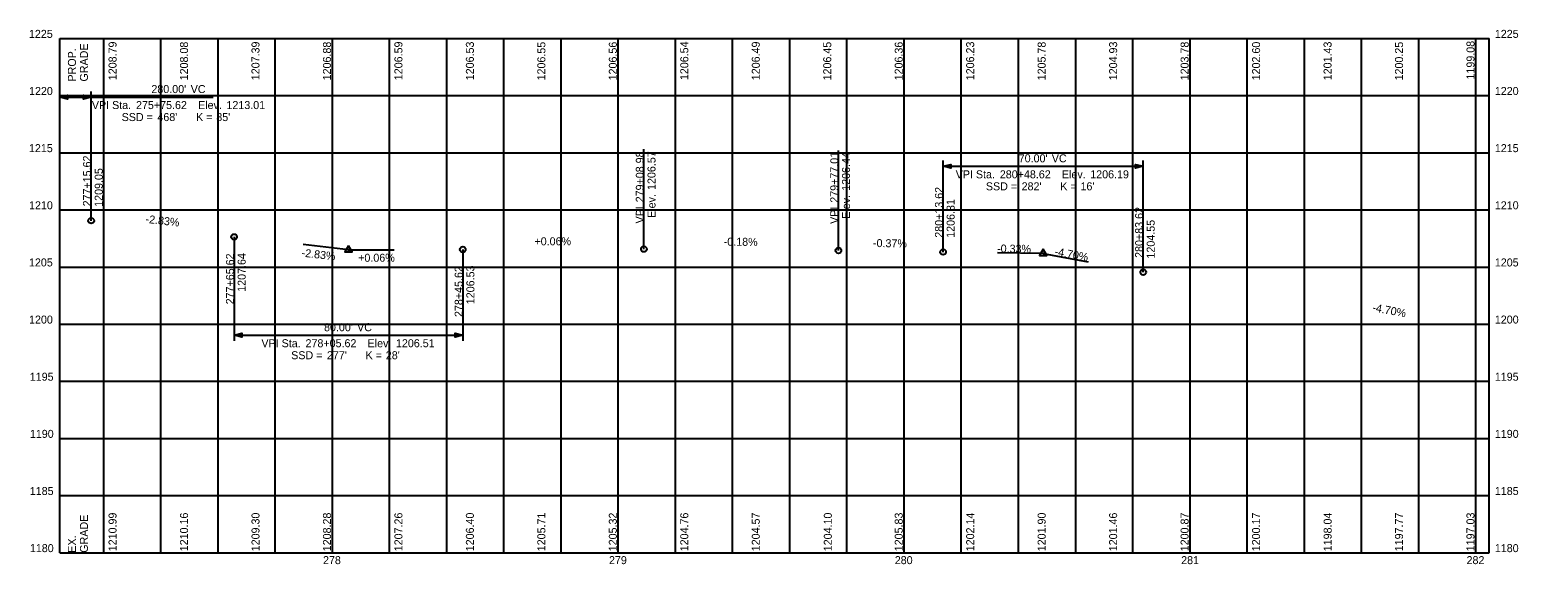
# Model space of a CAD drawing. Extents: x 894 to 1415, y 1176 to 1363.
import ezdxf

# ---------------------------------------------------------------- set-up
doc = ezdxf.new("R2010")
doc.units = 0
for name, color, linetype in [('GE_P_Alignment_100_Bearings', 7, 'Continuous'), ('GE_P_Alignment_100_Cardinal_Points', 7, 'Continuous'), ('GE_P_Alignment_100_Curve_Data', 7, 'Continuous'), ('GE_P_Alignment_100_Stations', 7, 'Continuous'), ('PF_P_Grade_Line', 7, 'Continuous'), ('SC_Scratch1', 7, 'Continuous')]:
    doc.layers.add(name, color=color, linetype=linetype)

msp = doc.modelspace()

# ---------------------------------------------------------------- linework, layer by layer
at = {"layer": 'GE_P_Alignment_100_Bearings'}
for p, q in [((904.62, 1360), (1404.62, 1360)), ((904.62, 1180), (904.62, 1360)), ((920, 1180), (920, 1360)), ((940, 1180), (940, 1360)), ((960, 1180), (960, 1360)), ((980, 1180), (980, 1360)), ((1000, 1180), (1000, 1360)), ((1020, 1180), (1020, 1360)), ((1040, 1180), (1040, 1360)), ((1060, 1180), (1060, 1360)), ((1080, 1180), (1080, 1360)), ((1100, 1180), (1100, 1360)), ((1120, 1180), (1120, 1360)), ((1140, 1180), (1140, 1360)), ((1160, 1180), (1160, 1360)), ((1180, 1180), (1180, 1360)), ((1200, 1180), (1200, 1360)), ((1220, 1180), (1220, 1360)), ((1240, 1180), (1240, 1360)), ((1260, 1180), (1260, 1360)), ((1280, 1180), (1280, 1360)), ((1300, 1180), (1300, 1360)), ((1320, 1180), (1320, 1360)), ((1340, 1180), (1340, 1360)), ((1360, 1180), (1360, 1360)), ((1380, 1180), (1380, 1360)), ((1400, 1180), (1400, 1360)), ((1404.62, 1180), (1404.62, 1360)), ((904.62, 1340), (1404.62, 1340)), ((904.62, 1320), (1404.62, 1320)), ((904.62, 1300), (1404.62, 1300)), ((904.62, 1280), (1404.62, 1280)), ((904.62, 1260), (1404.62, 1260)), ((904.62, 1240), (1404.62, 1240)), ((904.62, 1220), (1404.62, 1220)), ((904.62, 1200), (1404.62, 1200)), ((904.62, 1180), (1404.62, 1180))]:
    msp.add_line(p, q, dxfattribs=at)
at = {"layer": 'GE_P_Alignment_100_Curve_Data'}
for p, q in [((904.62, 1339.58), (904.62, 1339.38)), ((904.62, 1339.48), (915.62, 1339.48)), ((915.62, 1296.21), (915.62, 1341.48)), ((915.62, 1339.38), (915.62, 1339.58)), ((1108.98, 1286.27), (1108.98, 1321.27)), ((1177.01, 1285.78), (1177.01, 1320.78)), ((1213.62, 1285.24), (1213.62, 1317.24)), ((1213.62, 1315.34), (1213.62, 1315.14)), ((1213.62, 1315.24), (1283.62, 1315.24)), ((1283.62, 1278.19), (1283.62, 1317.24)), ((1283.62, 1315.14), (1283.62, 1315.34)), ((965.62, 1290.55), (965.62, 1254.12)), ((1005.62, 1286.02), (989.73, 1287.82)), ((1005.62, 1286.02), (1021.62, 1286.06)), ((1045.62, 1286.12), (1045.62, 1254.12)), ((1005.62, 1286.02), (1005.62, 1286.02)), ((1248.62, 1284.77), (1232.63, 1284.99)), ((1248.62, 1284.77), (1248.62, 1284.77)), ((1248.62, 1284.77), (1264.35, 1281.82)), ((965.62, 1256.22), (965.62, 1256.02)), ((965.62, 1256.12), (1045.62, 1256.12)), ((1045.62, 1256.02), (1045.62, 1256.22))]:
    msp.add_line(p, q, dxfattribs=at)
for points in [[(904.62, 1339.48), (907.34, 1340.16), (907.34, 1338.8)], [(915.62, 1339.48), (912.91, 1338.8), (912.91, 1340.16)], [(1213.62, 1315.24), (1216.34, 1315.92), (1216.34, 1314.56)], [(1283.62, 1315.24), (1280.91, 1314.56), (1280.91, 1315.92)], [(1005.62, 1287.46), (1004.37, 1285.3), (1006.87, 1285.3)], [(1248.62, 1286.22), (1247.37, 1284.05), (1249.87, 1284.05)], [(965.62, 1256.12), (968.34, 1256.8), (968.34, 1255.44)], [(1045.62, 1256.12), (1042.91, 1255.44), (1042.91, 1256.8)]]:
    msp.add_lwpolyline(points, close=True, dxfattribs=at)
for centre, radius in [((915.62, 1296.21), 1), ((965.62, 1290.55), 1), ((1005.62, 1286.02), 0.1), ((1005.62, 1286.02), 0.1), ((1045.62, 1286.12), 1), ((1108.98, 1286.27), 1), ((1177.01, 1285.78), 1), ((1213.62, 1285.24), 1), ((1248.62, 1284.77), 0.1), ((1248.62, 1284.77), 0.1), ((1283.62, 1278.19), 1)]:
    msp.add_circle(centre, radius, dxfattribs=at)
at = {"layer": 'PF_P_Grade_Line'}
msp.add_line((915.62, 1339.48), (958.31, 1339.48), dxfattribs=at)

# ---------------------------------------------------------------- texts
at = {"layer": 'GE_P_Alignment_100_Cardinal_Points'}
for s, p in [('1225', (893.86, 1360.2)), ('1225', (1406.62, 1360.2)), ('1220', (893.89, 1340.2)), ('1220', (1406.62, 1340.2)), ('1215', (893.86, 1320.2)), ('1215', (1406.62, 1320.2)), ('1210', (893.89, 1300.2)), ('1210', (1406.62, 1300.2)), ('1205', (893.86, 1280.2)), ('1205', (1406.62, 1280.2)), ('1200', (893.89, 1260.2)), ('1200', (1406.62, 1260.2)), ('1195', (894.15, 1240.2)), ('1195', (1406.62, 1240.2)), ('1190', (894.18, 1220.2)), ('1190', (1406.62, 1220.2)), ('1185', (894.15, 1200.2)), ('1185', (1406.62, 1200.2)), ('1180', (894.18, 1180.2)), ('1180', (1406.62, 1180.2)), ('278', (996.72, 1176)), ('279', (1096.75, 1176)), ('280', (1196.72, 1176)), ('281', (1296.89, 1176)), ('282', (1396.73, 1176))]:
    msp.add_text(s, height=2.8, dxfattribs=at).set_placement(p)
at = {"layer": 'GE_P_Alignment_100_Curve_Data'}
for s, rotation, p in [('PROP.', 90, (910.3, 1344.92)), ('GRADE', 90, (914.5, 1344.92)), ('277+15.62', 90, (915.58, 1301.21)), ('279+08.98', 90, (1108.94, 1302.64)), ('1206.57', 90, (1113.03, 1306.97)), ('279+77.01', 90, (1176.97, 1302.49)), ('1206.44', 90, (1181.06, 1306.67)), ('1209.05', 90, (919.67, 1301.07)), ('280+13.62', 90, (1213.58, 1290.24)), ('Elev. ', 90, (1113.03, 1297.19)), ('Elev. ', 90, (1181.06, 1296.89)), ('1206.31', 90, (1217.67, 1290.22)), ('-2.83%', 353.5416, (934.54, 1295.47)), ('VPI ', 90, (1108.94, 1295.25)), ('VPI ', 90, (1176.97, 1295.09)), ('280+83.62', 90, (1283.58, 1283.19)), ('1204.55', 90, (1287.65, 1282.96)), ('-2.83%', 353.5416, (989.13, 1283.66)), ('+0.06%', 0.1375, (1070.69, 1287.58)), ('-0.18%', 359.5875, (1136.88, 1287.47)), ('-0.37%', 359.1521, (1189.09, 1287)), ('-0.33%', 359.2437, (1232.5, 1285.09)), ('-4.70%', 349.3527, (1252.45, 1284.16)), ('277+65.62', 90, (965.58, 1266.93)), ('1207.64', 90, (969.67, 1271.32)), ('+0.06%', 0.1375, (1009.02, 1281.83)), ('278+45.62', 90, (1045.58, 1262.5)), ('1206.53', 90, (1049.67, 1266.98)), ('-4.70%', 349.3527, (1363.61, 1264.56)), ('GRADE', 90, (914.5, 1179.99)), ('EX. ', 90, (910.3, 1179.99))]:
    msp.add_text(s, height=2.8, rotation=rotation, dxfattribs=at).set_placement(p)
for s, p in [("280.00'", (936.69, 1340.88)), (' VC', (949.4, 1340.88)), ('VPI Sta. ', (915.87, 1335.28)), ('275+75.62', (931.31, 1335.28)), ('   Elev. ', (949.9, 1335.28)), ('1213.01', (962.94, 1335.28)), ('SSD = ', (926.29, 1331.08)), ("468'", (938.79, 1331.08)), ('K = ', (952.32, 1331.08)), ("85'", (959.39, 1331.08)), ("70.00'", (1240.08, 1316.64)), (' VC', (1250.61, 1316.64)), ('VPI Sta. ', (1218.03, 1311.04)), ('280+48.62', (1233.47, 1311.04)), ('   Elev. ', (1252.06, 1311.04)), ('1206.19', (1265.1, 1311.04)), ('SSD = ', (1228.59, 1306.84)), ("282'", (1241.09, 1306.84)), ('K = ', (1254.62, 1306.84)), ("16'", (1261.69, 1306.84)), ("80.00'", (997.08, 1257.52)), (' VC', (1007.61, 1257.52)), ('   Elev. ', (1009.2, 1251.92)), ('VPI Sta. ', (975.17, 1251.92)), ('SSD = ', (985.59, 1247.72)), ('278+05.62', (990.61, 1251.92)), ("277'", (998.09, 1247.72)), ('K = ', (1011.62, 1247.72)), ("28'", (1018.69, 1247.72)), ('1206.51', (1022.24, 1251.92))]:
    msp.add_text(s, height=2.8, dxfattribs=at).set_placement(p)
at = {"layer": 'GE_P_Alignment_100_Stations'}
for s, p in [('1210.99', (924.5, 1180.5)), ('1210.16', (949.5, 1180.5)), ('1209.30', (974.51, 1180.5)), ('1208.28', (999.51, 1180.5)), ('1207.26', (1024.5, 1180.5)), ('1206.40', (1049.5, 1180.5)), ('1205.71', (1074.5, 1180.5)), ('1205.32', (1099.5, 1180.5)), ('1204.76', (1124.5, 1180.5)), ('1204.57', (1149.5, 1180.5)), ('1204.10', (1174.7, 1180.5)), ('1205.83', (1199.51, 1180.5)), ('1202.14', (1224.5, 1180.5)), ('1201.90', (1249.5, 1180.5)), ('1201.46', (1274.5, 1180.5)), ('1200.87', (1299.5, 1180.5)), ('1200.17', (1324.5, 1180.5)), ('1198.04', (1349.54, 1180.5)), ('1197.77', (1374.5, 1180.5)), ('1197.03', (1399.5, 1180.5))]:
    msp.add_text(s, height=2.8, rotation=90, dxfattribs=at).set_placement(p)
at = {"layer": 'SC_Scratch1'}
for s, p in [('1199.08', (1399.51, 1345.62)), ('1199.08', (1399.51, 1345.62)), ('1208.79', (924.5, 1345.38)), ('1208.79', (924.5, 1345.38)), ('1208.08', (949.5, 1345.33)), ('1208.08', (949.5, 1345.33)), ('1207.39', (974.5, 1345.38)), ('1207.39', (974.5, 1345.38)), ('1206.88', (999.5, 1345.33)), ('1206.88', (999.5, 1345.33)), ('1206.59', (1024.5, 1345.38)), ('1206.59', (1024.5, 1345.38)), ('1206.53', (1049.5, 1345.36)), ('1206.53', (1049.5, 1345.36)), ('1206.55', (1074.5, 1345.3)), ('1206.55', (1074.5, 1345.3)), ('1206.56', (1099.5, 1345.32)), ('1206.56', (1099.5, 1345.32)), ('1206.54', (1124.5, 1345.41)), ('1206.54', (1124.5, 1345.41)), ('1206.49', (1149.5, 1345.38)), ('1206.49', (1149.5, 1345.38)), ('1206.45', (1174.5, 1345.3)), ('1206.45', (1174.5, 1345.3)), ('1206.36', (1199.5, 1345.32)), ('1206.36', (1199.5, 1345.32)), ('1206.23', (1224.5, 1345.36)), ('1206.23', (1224.5, 1345.36)), ('1205.78', (1249.5, 1345.33)), ('1205.78', (1249.5, 1345.33)), ('1204.93', (1274.51, 1345.36)), ('1204.93', (1274.51, 1345.36)), ('1203.78', (1299.51, 1345.33)), ('1203.78', (1299.51, 1345.33)), ('1202.60', (1324.51, 1345.33)), ('1202.60', (1324.51, 1345.33)), ('1201.43', (1349.51, 1345.36)), ('1201.43', (1349.51, 1345.36)), ('1200.25', (1374.51, 1345.3)), ('1200.25', (1374.51, 1345.3))]:
    msp.add_text(s, height=2.8, rotation=90, dxfattribs=at).set_placement(p)

doc.saveas('drawing.dxf')
